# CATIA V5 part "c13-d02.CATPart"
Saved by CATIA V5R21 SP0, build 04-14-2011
Part number: Part1
Bounding box of the stored display mesh (mm): x -33 to 33, y -200.819 to 48, z -35 to 35
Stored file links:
  D:\CATIA V5R21 E-RESOURCES\CATIA-V5R21\catia-v5r21-prt\c13-catia-v5r20-prt\c13-catia-v5r20-figr-13-17\c13-d02.CATPart
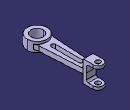
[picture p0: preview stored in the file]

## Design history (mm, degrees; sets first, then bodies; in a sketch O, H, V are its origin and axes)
Body1 (main body)
  Sketch1 on yz-plane, origin (0, 0, 0), H (0, 1, 0), V (0, 0, 1)
    line L1 (0, 0) -> (0, -35)
    point P1 (0, -35)
    line L2 (0, -35) -> (48, -35)
    point P2 (48, -35)
    line L3 (48, -35) -> (48, -25)
    point P3 (48, -25)
    line L4 (48, -25) -> (10, -25)
    point P4 (10, -25)
    line L5 (10, -25) -> (10, 0)
    point P5 (10, 0)
    point P6 (0, 0)
    point P7 (0, 0)
    point P8 (0, 35)
    point P9 (48, 35)
    point P10 (48, 25)
    point P11 (10, 25)
    point P12 (10, 0)
    point P13 (0, 0)
    line L6 (0, 0) -> (0, 35)
    line L7 (0, 35) -> (48, 35)
    line L8 (48, 35) -> (48, 25)
    line L9 (48, 25) -> (10, 25)
    line L10 (10, 25) -> (10, 0)
    length L8 = 10
    distance P3 L9 = 50
    length L2 = 48
    distance L10 L6 = 10
    vertical: L1 V, L3 V, L5 V
    horizontal: L2 H, L4 H
    symmetry: O P7 H, P1 P8 H, P2 P9 H, P3 P10 H, P4 P11 H, P5 P12 H, P6 P13 H, L1 L6 H, L2 L7 H, L3 L8 H, L4 L9 H, L5 L10 H
    coincidence: P13 P7, P12 P5, P6 P7
  Pad1: profile Sketch1, direction (1, 0, 0), length 16, mirrored extent
  Sketch2 on xy-plane, origin (0, 0, 0), H (1, 0, 0), V (0, 1, 0)
    circle A1 centre (0, -168) radius 33
    point P1 (0, -168)
    circle A2 centre (0, -168) radius 20
    distance P1 H = 168
    radius A1 = 33
    radius A2 = 20
    coincidence: P1 V
  Pad2: profile Sketch2, direction (0, 0, 1), length 16, mirrored extent
  Sketch3 on xy-plane, origin (0, 0, 0), H (1, 0, 0), V (0, 1, 0)
    line L1 (-16, 0) -> (-25, -146.4593)
    point P1 (-16, 0)
    point P2 (-25, -146.4593)
    line L2 (16, 0) -> (25, -146.4593)
    point P3 (16, 0)
    point P4 (25, -146.4593)
    reference projected line E1 (16, 48) -> (16, 0) from edge [face of Pad1 | face of Pad1]
    reference projected line E2 (-16, 48) -> (-16, 0) from edge [face of Pad1 | face of Pad1]
    projected circle E3 centre (0, -168) radius 33 from edge [face of Pad2 | face of Pad2]
    projected arc E4 centre (0, -168) radius 33 from (25, -146.4593) to (-25, -146.4593) ccw from edge [face of Pad2 | face of Pad2]
    line L3 (-16, 0) -> (16, 0)
    distance P4 P2 H = 50
    coincidence: P1 H, P3 H, P3 E1, P1 E2, P2 E3, P4 E3
    symmetry: P4 P2 V
    horizontal: L3 H
  Pad3: profile Sketch3, direction (0, 0, 1), length 8, mirrored extent
  Fillet1: radius 6, on edge [face of Pad1 | face of Pad3]; edge [face of Pad3 | face of Pad1]; edge [face of Pad1 | face of Pad1] (x2)
  Fillet2: radius 30, on edge [face of Pad3 | face of Pad2]; edge [face of Pad2 | face of Pad3]
  TritangentFillet1: Face1 face of Pad1, Face2 face of Pad1, RemoveFace face of Pad1
  TritangentFillet2: Face1 face of Pad1, Face2 face of Pad1, RemoveFace face of Pad1
  Sketch4 on face of Pad1, origin (2.8418, 32, 35), H (1, 0, 0), V (0, 1, 0)
    point P1 (-2.8418, 0)
    reference projected arc E1 centre (-2.8418, 0) radius 16 from (13.1582, 0) to (-18.8418, 0) ccw from edge [face of Pad1 | face of TritangentFillet1]
    concentricity: P1 E1
  Hole1: placed by Sketch4, at (0, 32, 35) direction (0, 0, -1), diameter 16, through (limit type 3)
  Sketch5 on face of Pad3, origin (0, 0, 8), H (1, 0, 0), V (0, 1, 0)
    construction line L1 (0, -25) -> (0, -115)
    point P1 (0, -25)
    line L2 (7, -25) -> (7, -115)
    line L3 (-7, -115) -> (-7, -25)
    arc A1 centre (0, -115) radius 7 from (7, -115) to (-7, -115) cw
    arc A2 centre (0, -25) radius 7 from (-7, -25) to (7, -25) cw
    distance P1 H = 25
    length L1 = 90
    radius A1 = 7
    coincidence: P1 V
    vertical: L1 V
    tangency: A1 L2, A2 L2, A1 L3, A2 L3
    parallelism: L1 L2
  Pocket1: profile Sketch5, direction (0, 0, -1), through (limit type 3)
